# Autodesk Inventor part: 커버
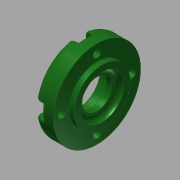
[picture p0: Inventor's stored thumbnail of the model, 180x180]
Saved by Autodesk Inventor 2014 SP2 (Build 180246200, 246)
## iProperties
Created: 2015-11
Part Number: 커버
Material: 알루미늄 6061
Document SubType Name: Modeling
Designer: mduedu
Density: 1 g/cm^3
Appearance: 매끄러움 - 짙은 산림 녹색
Author: mduedu
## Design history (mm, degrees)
sketch "스케치1"
  geometry: L1 (-7, 0)-(7, 0); L2 (-7, 0)-(-7, 25); L3 (-7, 25)-(4, 25); L4 (4, 25)-(4, 16); L5 (4, 16)-(7, 16); L6 (7, 16)-(7, 0); 2 further points
  constraints: 12 end point, 3 perpendicular, 2 parallel, 1 coincident, 1 horizontal, 1 midpoint
  dimensions: "d0" = 14 distance of L1.start L1.end; "d1" = 50 diameter of L3 L1; "d2" = 3 distance of L4.end L5.end; "d3" = 32 diameter of L5 L1
revolve "회전1" sketch "스케치1" stored, may be unused: angle "d4" = 90 deg
hole "구멍1" diameter "d7" = 25; stored, may be unused: countersink angle "d11" = 90 deg, drill point angle "d13" = 0 deg; dims "d5" = 10, "d6" = 10, "d8" = 6, "d9" = 4, "d10" = 2, "d12" = 3
hole "구멍2" diameter "d16" = 25; stored, may be unused: countersink angle "d20" = 90 deg, drill point angle "d22" = 0 deg; dims "d17" = 6, "d18" = 4, "d19" = 2, "d21" = 7.7, "d58" = 10, "d59" = 10
hole "구멍3" diameter "d25" = 17; stored, may be unused: countersink angle "d29" = 90 deg, drill point angle "d31" = 0 deg; dims "d23" = 10, "d24" = 10, "d26" = 6, "d27" = 4, "d28" = 2, "d30" = 4.2
chamfer "모따기1" distance "d32" = 0.6; stored, may be unused: second distance "d33" = 2, angle "d34" = 30 deg
fillet "모깎기1" dims "d35" = 0.3
fillet "모깎기2" dims "d36" = 3
fillet "모깎기3" dims "d37" = 3
fillet "모깎기4" dims "d38" = 0.3
sketch "스케치2" dims "d39" = 40
  geometry: 6 further points
  constraints: 2 vertical alignment, 1 coincident, 7 other
  dimensions: "d42" = 360 deg dimension on point (0, 0) point (0, 20) (derived)
sketch "스케치3"
  geometry: 4 further points
hole "구멍4" sketch "스케치3" at (-20, 0), (0, -20), (20, 0), (0, 20) diameter "d44" = 4.5; stored, may be unused: countersink angle "d48" = 90 deg, drill point angle "d50" = 0 deg; dims "d45" = 6, "d46" = 8, "d47" = 4.6, "d49" = 8
sketch "스케치4"
  geometry: L1 (-4, 0)-(-4, -4.678); L2 (4, 0)-(4, -4.678); A1 r 4 centre (0, 0) between (3.621, -1.7) and (-3.621, -1.7) reference; A2 r 25 centre (0, 20) between (-4, -4.678) and (4, -4.678) reference; 1 further point
  constraints: 4 end point, 4 point on circle, 2 tangent, 1 parallel, 1 vertical
extrude "돌출1" cut sketch "스케치4" stored distance "d51" = 0; taper "d52" = 0 deg
fillet "모깎기5" dims "d56" = 0.3
fillet "모깎기6" dims "d57" = 1
node "솔리드1"
pattern_circular "원형 패턴1" dims angle "d54" = 360 deg
